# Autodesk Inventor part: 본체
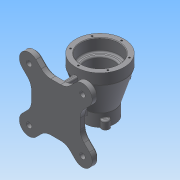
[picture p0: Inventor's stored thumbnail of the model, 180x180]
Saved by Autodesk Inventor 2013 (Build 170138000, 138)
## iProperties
Created: 2018-03
Part Number: 본체
Material: 일반
Document SubType Name: Modeling
Designer: Administrator
Density: 1 g/cm^3
Author: Administrator
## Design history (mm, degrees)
sketch "스케치1"
  geometry: L1 (45, 50)-(35, 50); L2 (35, 50)-(35, 27); L3 (35, 27)-(26, 27); L4 (26, 27)-(26, -20); L5 (26, -20)-(20, -20); L6 (20, -20)-(20, -50); L7 (20, -50)-(27.5, -50); L8 (27.5, -50)-(27.5, -27); L9 (27.5, -27)-(45, 30); L10 (45, 30)-(45, 50); L11 (0, 0)-(0, 61.227)
  constraints: 22 end point, 7 parallel, 1 horizontal, 1 perpendicular, 1 vertical
  dimensions: "d14" = 50 distance from line of L11.start L1; "d15" = 20 distance of L9.end L1.start; "d16" = 77 distance from line of L8.end L1; "d17" = 100 distance between parallel lines of L7 L1; "d18" = 23 distance of L1.end L2.end; "d19" = 47 distance of L3.end L4.end; "d20" = 40 diameter of L6 L11; "d21" = 55 diameter of L8 L11; "d22" = 90 diameter of L10 L11; "d23" = 70 diameter of L2 L11; "d24" = 52 diameter of L4 L11
revolve "회전1" sketch "스케치1" stored, may be unused: angle "d25" = 90 deg
node "작업 평면1"
sketch "스케치3"
  geometry: L1 (45, 45)-(-45, 45); L2 (-45, 45)-(-45, -45); L3 (-45, -45)-(45, -45); L4 (45, -45)-(45, 45); L5 (0, 0)-(65.909, 65.909); L6 (0, 0)-(114.42, 0); L7 (36.77, 62.225)-(19.544, 45); L8 (62.225, 36.77)-(45, 19.544); L9 (0, 0)-(73.646, -73.646); L10 (0, 0)-(-84.879, -84.879); L11 (0, 0)-(-79.002, 79.002); L12 (-36.77, 62.225)-(-19.544, 45); L13 (45, -19.544)-(62.225, -36.77); L14 (19.544, -45)-(36.77, -62.225); L15 (-19.544, -45)-(-36.77, -62.225); L16 (-45, -19.544)-(-62.225, -36.77); L17 (-45, 19.544)-(-62.225, 36.77); A1 r 70 centre (0, 0) between (49.497, 49.497) and (49.497, -49.497); A2 r 18 centre (49.497, 49.497) between (62.225, 36.77) and (36.77, 62.225); A3 r 18 centre (-49.497, 49.497) between (-36.77, 62.225) and (-62.225, 36.77); A4 r 18 centre (-49.497, -49.497) between (-62.225, -36.77) and (-36.77, -62.225); A5 r 18 centre (49.497, -49.497) between (36.77, -62.225) and (62.225, -36.77); 3 further points
  constraints: 34 end point, 12 point on circle, 12 point on line, 10 parallel, 8 tangent, 5 centre point, 3 perpendicular, 2 midpoint, 1 coincident, 1 horizontal, 1 horizontal alignment, 1 vertical alignment
  dimensions: "d46" = 90 distance of L1.start L1.end; "d48" = 90 distance of L3.end L1.start; "d49" = 140 diameter of A1; "d50" = 45 deg angle of L6 L5; "d52" = 18 radius of A2; "d53" = 90 deg angle of L10 L9; "d54" = 90 deg angle of L10 L11; "d58" = 18 radius of A5; "d59" = 18 radius of A3; "d60" = 18 radius of A4
extrude "돌출3" join sketch "스케치3" distance "d61" = 12; taper "d62" = 0 deg
sketch "스케치4"
  geometry: L1 (-24, -4)-(24, -4); L2 (24, -4)-(24, 4); L3 (24, 4)-(-24, 4); L4 (-24, 4)-(-24, -4); L5 (-4, -37)-(4, -37); L6 (4, -37)-(4, 37); L7 (4, 37)-(-4, 37); L8 (-4, 37)-(-4, -37); 4 further points
  constraints: 16 end point, 4 parallel, 3 midpoint, 2 horizontal, 2 perpendicular, 2 vertical alignment, 1 horizontal alignment
  dimensions: "d64" = 37 distance from line of point (0, 0) L5; "d65" = 37 distance from line of point (0, 0) L7; "d67" = 48 distance between parallel lines of L2 L4; "d68" = 8 distance between parallel lines of L6 L8; "d69" = 8 distance between parallel lines of L3 L1
extrude "돌출4" join sketch "스케치4" stored distance "d70" = 12; taper "d71" = 0 deg
feature "면 기울기1" dims angle "d72" = 5 deg
node "작업 평면2"
sketch "스케치5"
  geometry: L1 (-12.5, 12.5)-(12.5, 12.5); L2 (12.5, 12.5)-(12.5, -12.5); L3 (12.5, -12.5)-(-12.5, -12.5); L4 (-12.5, -12.5)-(-12.5, 12.5); L5 (-7.5, 7.5)-(7.5, 7.5); L6 (7.5, 7.5)-(7.5, -7.5); L7 (7.5, -7.5)-(-7.5, -7.5); L8 (-7.5, -7.5)-(-7.5, 7.5); 5 further points
  constraints: 16 end point, 4 midpoint, 4 parallel, 2 horizontal, 2 horizontal alignment, 2 perpendicular, 2 vertical alignment
  dimensions: "d74" = 25 distance of L3.end L1.start; "d76" = 25 distance of L1.start L1.end; "d77" = 15 distance of L5.end L6.end; "d78" = 15 distance of L6.end L7.end
extrude "돌출5" join sketch "스케치5" stored distance "d79" = 0; taper "d80" = 0 deg
extrude "돌출6" cut sketch "스케치5" stored distance "d81" = 12; taper "d82" = 0 deg
sketch "스케치6"
  geometry: L1 (0, 0)-(0, 27.5); L2 (0, 0)-(23.816, -13.75); L3 (0, 0)-(-23.816, -13.75); C1 r 7 at (0, 27.5); C2 r 7 at (-23.816, -13.75); C3 r 7 at (23.816, -13.75); A1 r 27.5 centre (0, 0) between (23.816, -13.75) and (-23.816, -13.75) reference
  constraints: 6 end point, 3 centre point, 3 coincident, 3 point on circle, 2 equal radius, 1 vertical
  dimensions: "d83" = 120 deg angle of L1 L3; "d84" = 120 deg angle of L1 L2; "d85" = 14 diameter of C1
extrude "돌출7" join sketch "스케치6" distance "d87" = 15; taper "d88" = 0 deg
hole "구멍1" diameter "d91" = 10; stored, may be unused: countersink angle "d95" = 90 deg, drill point angle "d97" = 118 deg; dims "d89" = 10, "d90" = 10, "d92" = 6, "d93" = 4, "d94" = 2, "d96" = 8
hole "구멍2" diameter "d100" = 10; stored, may be unused: countersink angle "d104" = 90 deg, drill point angle "d106" = 118 deg; dims "d98" = 10, "d99" = 10, "d101" = 6, "d102" = 4, "d103" = 2, "d105" = 8
hole "구멍3" diameter "d109" = 10; stored, may be unused: countersink angle "d113" = 90 deg, drill point angle "d115" = 118 deg; dims "d107" = 10, "d108" = 10, "d110" = 6, "d111" = 4, "d112" = 2, "d114" = 8
hole "구멍4" diameter "d118" = 10; stored, may be unused: countersink angle "d122" = 90 deg, drill point angle "d124" = 118 deg; dims "d116" = 10, "d117" = 10, "d119" = 6, "d120" = 4, "d121" = 2, "d123" = 8
sketch "스케치7"
  geometry: C1 r 45 at (0, 0) reference; 1 further point
  constraints: 1 vertical alignment
  dimensions: "d125" = 40 distance of C1.centre point (0, 40)
hole "구멍5" sketch "스케치7" at (0, 40) diameter "d126" = 3.242; stored, may be unused: countersink angle "d130" = 90 deg, drill point angle "d132" = 118 deg; dims "d127" = 9, "d128" = 4, "d129" = 2, "d131" = 11
hole "구멍6" diameter "d138" = 3.242; stored, may be unused: countersink angle "d142" = 90 deg, drill point angle "d144" = 118 deg; dims "d136" = 10, "d137" = 10, "d139" = 9, "d140" = 4, "d141" = 2, "d143" = 11
fillet "모깎기1" dims "d148" = 3
fillet "모깎기2" dims "d149" = 3
fillet "모깎기3" dims "d150" = 8, "d151" = 3
fillet "모깎기4" dims "d152" = 1
fillet "모깎기5" dims "d153" = 3
fillet "모깎기6" dims "d154" = 1
fillet "모깎기8" dims "d156" = 25
fillet "모깎기7" dims "d155" = 3
fillet "모깎기9" dims "d157" = 3
chamfer "모따기1" distance "d159" = 1; stored, may be unused: second distance "d160" = 2, angle "d161" = 45 deg
sketch "스케치9"
  geometry: 2 further points
  constraints: 1 horizontal alignment, 1 other
  dimensions: "d162" = 35 distance of point (0, 0) point (35, 0)
feature "엠보싱1" sketch "스케치9" dims "d163" = 0.5, "d164" = 0
chamfer "모따기2" distance "d165" = 3; stored, may be unused: second distance "d166" = 2, angle "d167" = 45 deg
chamfer "모따기3" distance "d168" = 1; stored, may be unused: second distance "d169" = 2, angle "d170" = 45 deg
node "솔리드1"
pattern_circular "원형 패턴1" dims angle "d134" = 360 deg
pattern_circular "원형 패턴2" dims angle "d146" = 360 deg
other parameters: "d26" = -82, "d51" = 36, "d55" = 36, "d56" = 36, "d57" = 36, "d73" = 45
